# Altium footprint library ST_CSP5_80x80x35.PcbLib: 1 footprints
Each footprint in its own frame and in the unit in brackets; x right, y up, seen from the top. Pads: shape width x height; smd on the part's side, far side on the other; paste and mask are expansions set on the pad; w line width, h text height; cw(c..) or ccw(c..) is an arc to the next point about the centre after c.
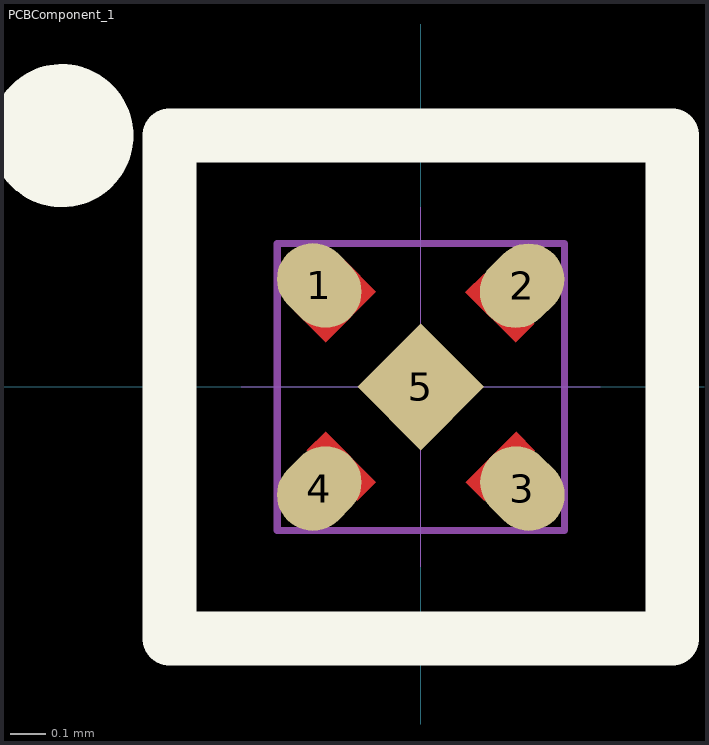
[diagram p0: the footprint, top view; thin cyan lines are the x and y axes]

## PCBComponent_1 [mm]
pads (5):
  rrect100% 0.2x0.25 smd rot 45 paste+0 mask+0.05: 1(-0.283,0.283) 3(0.283,-0.283)
  rrect100% 0.2x0.25 smd rot 135 paste+0 mask+0.05: 2(0.282,0.282) 4(-0.283,-0.283)
  rect 0.25x0.25 smd rot 45 paste+0 mask+0.05: 5(0,0)
Top Layer:
  region: -0.318,-0.177 -0.177,-0.318 -0.124,-0.265 -0.265,-0.124
  region: 0.124,-0.265 0.177,-0.318 0.318,-0.177 0.265,-0.124
  region: 0.123,0.264 0.264,0.123 0.317,0.176 0.176,0.317
  region: -0.353,0.213 -0.265,0.124 -0.124,0.265 -0.212,0.354
Top Overlay:
  circle w0.254: c-1,0.7 r0.072
  lines w0.15: -0.7,-0.7 -0.7,0.7 0.7,0.7 0.7,-0.7 -0.7,-0.7
Top Paste:
  region: 0.123,0.264 0.264,0.123 0.441,0.3 0.3,0.441
  region: -0.442,0.301 -0.265,0.124 -0.124,0.265 -0.301,0.442
  region: 0.124,-0.265 0.301,-0.442 0.442,-0.301 0.265,-0.124
  region: -0.442,-0.301 -0.301,-0.442 -0.124,-0.265 -0.265,-0.124
Top Solder:
  region: -0.4,-0.188 -0.188,-0.4 -0.053,-0.265 -0.265,-0.053
  region: 0.053,-0.265 0.188,-0.4 0.4,-0.188 0.265,-0.053
  region: 0.052,0.264 0.264,0.052 0.36,0.148 0.148,0.36
  region: -0.4,0.188 -0.265,0.053 -0.053,0.265 -0.188,0.4
Mechanical 1:
  lines w0.001: -0.5,0 0.5,0 ; 0,-0.5 0,0.5
Mechanical 15:
  lines w0.02: -0.4,-0.4 0.4,-0.4 0.4,0.4 -0.4,0.4 -0.4,-0.4
3D body: height 0.38, standoff 0, extent -0.4,-0.4 0.4,0.4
